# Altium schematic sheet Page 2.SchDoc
size 431 x 279 mm; Date: Not shown in title block; ApprovedBy: Not shown in title block; CheckedBy: Not shown in title block; Author: Not shown in title block; CompanyName: Not shown in title block; Engineer: Not shown in title block; Organization: Not shown in title block; Address1: Not shown in title block; Address2: Not shown in title block; Address3: Not shown in title block; Address4: Not shown in title block; DocumentNumber: 1; Revision: Use project parameter SCH_Rev; SheetNumber: 2; SheetTotal: 3; PageSetup: Record=PageOptions¦CenterHorizontal=True¦CenterVertical=True¦PrintScale=1.00¦XCorrection=1.00¦YCorrection=1.00¦PrintKind=0¦BorderSize=5000000¦LeftOffset=0¦BottomOffset=0¦Orientation=2¦PaperLength=1000¦PaperWidth=1000¦Scale=100¦PaperSource=15¦PrintQuality=600¦MediaType=1¦DitherType=10¦PaperKind=Letter¦PrintScaleMode=1
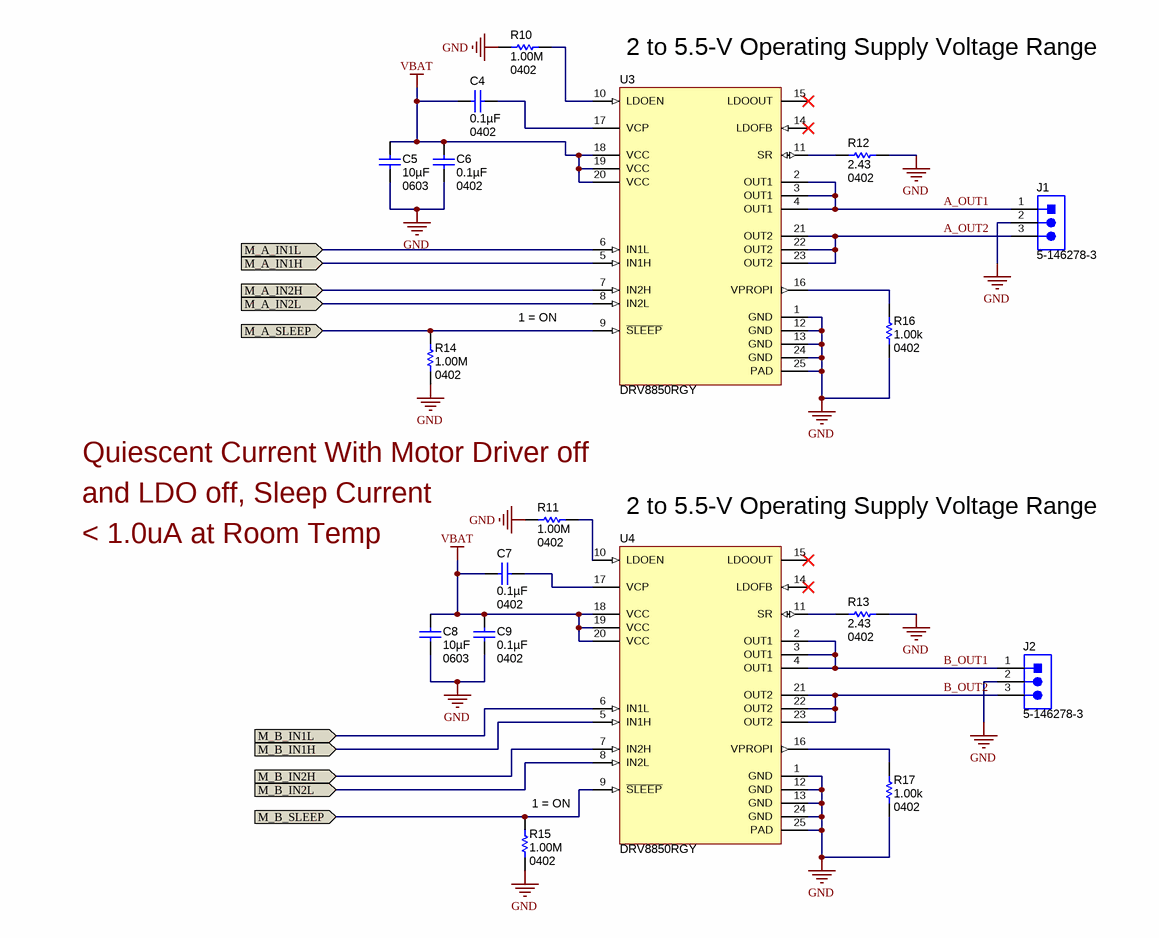
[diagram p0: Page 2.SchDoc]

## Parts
C4  ValueDisplayed: 0.1µF  PackageReference: 0402  [0402L]  (hidden comment: C1005X5R0J104K)
C5  ValueDisplayed: 10µF  PackageReference: 0603  [0603L]  (hidden comment: C1608X5R1E106M080AC)
C6  ValueDisplayed: 0.1µF  PackageReference: 0402  [0402L]  (hidden comment: C1005X5R0J104K)
C7  ValueDisplayed: 0.1µF  PackageReference: 0402  [0402L]  (hidden comment: C1005X5R0J104K)
C8  ValueDisplayed: 10µF  PackageReference: 0603  [0603L]  (hidden comment: C1608X5R1E106M080AC)
C9  ValueDisplayed: 0.1µF  PackageReference: 0402  [0402L]  (hidden comment: C1005X5R0J104K)
J1  5-146278-3  [TE_5-146278-3]
J2  5-146278-3  [TE_5-146278-3]
R10  ValueDisplayed: 1.00M  PackageReference: 0402  [0402L]  (hidden comment: CRCW04021M00FKED)
R11  ValueDisplayed: 1.00M  PackageReference: 0402  [0402L]  (hidden comment: CRCW04021M00FKED)
R12  ValueDisplayed: 2.43  PackageReference: 0402  [0402L]  (hidden comment: CRCW04022R43FKED)
R13  ValueDisplayed: 2.43  PackageReference: 0402  [0402L]  (hidden comment: CRCW04022R43FKED)
R14  ValueDisplayed: 1.00M  PackageReference: 0402  [0402L]  (hidden comment: CRCW04021M00FKED)
R15  ValueDisplayed: 1.00M  PackageReference: 0402  [0402L]  (hidden comment: CRCW04021M00FKED)
R16  ValueDisplayed: 1.00k  PackageReference: 0402  [0402L]  (hidden comment: ERJ-2RKF1001X)
R17  ValueDisplayed: 1.00k  PackageReference: 0402  [0402L]  (hidden comment: ERJ-2RKF1001X)
U3  DRV8850RGY  [RGY0024B]
U4  DRV8850RGY  [RGY0024B]

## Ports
M_A_IN1H (in), M_A_IN1L (in), M_A_IN2H (in), M_A_IN2L (in), M_A_SLEEP (in), M_B_IN1H (in), M_B_IN1L (in), M_B_IN2H (in), M_B_IN2L (in), M_B_SLEEP (in)

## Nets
GND: C5.2 C6.2 C8.2 C9.2 J1.2 J2.2 R10.2 R11.2 R12.1 R13.1 R14.1 R15.1 R16.1 R17.1 U3.1(GND) U3.12(GND) U3.13(GND) U3.24(GND) U3.25(PAD) U4.1(GND) U4.12(GND) U4.13(GND) U4.24(GND) U4.25(PAD)
VBAT: C4.2 C5.1 C6.1 C7.1 C8.1 C9.1 U3.18(VCC) U3.19(VCC) U3.20(VCC) U4.18(VCC) U4.19(VCC) U4.20(VCC)
A_OUT1: J1.1 U3.2(OUT1) U3.3(OUT1) U3.4(OUT1)
A_OUT2: J1.3 U3.21(OUT2) U3.22(OUT2) U3.23(OUT2)
B_OUT1: J2.1 U4.2(OUT1) U4.3(OUT1) U4.4(OUT1)
B_OUT2: J2.3 U4.21(OUT2) U4.22(OUT2) U4.23(OUT2)
M_A_IN1H: U3.5(IN1H) ; port M_A_IN1H
M_A_IN1L: U3.6(IN1L) ; port M_A_IN1L
M_A_IN2H: U3.7(IN2H) ; port M_A_IN2H
M_A_IN2L: U3.8(IN2L) ; port M_A_IN2L
M_A_SLEEP: R14.2 U3.9(~{SLEEP}) ; port M_A_SLEEP
M_B_IN1H: U4.5(IN1H) ; port M_B_IN1H
M_B_IN1L: U4.6(IN1L) ; port M_B_IN1L
M_B_IN2H: U4.7(IN2H) ; port M_B_IN2H
M_B_IN2L: U4.8(IN2L) ; port M_B_IN2L
M_B_SLEEP: R15.2 U4.9(~{SLEEP}) ; port M_B_SLEEP
NetC4_1: C4.1 U3.17(VCP)
NetC7_2: C7.2 U4.17(VCP)
NetR10_1: R10.1 U3.10(LDOEN)
NetR11_1: R11.1 U4.10(LDOEN)
NetR12_2: R12.2 U3.11(SR)
NetR13_2: R13.2 U4.11(SR)
NetR16_2: R16.2 U3.16(VPROPI)
NetR17_2: R17.2 U4.16(VPROPI)

Not connected (* = marked no-connect by the designer): U3 14(LDOFB)* 15(LDOOUT)*; U4 14(LDOFB)* 15(LDOOUT)*

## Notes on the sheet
- (near U3) 2 to 5.5-V Operating Supply Voltage Range
- 1 = ON
- Quiescent Current With Motor Driver off
- < 1.0uA at Room Temp
- and LDO off, Sleep Current
- 2 to 5.5-V Operating Supply Voltage Range
- (near R15) 1 = ON

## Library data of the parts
C4 C6 C7 C9 = C1005X5R0J104K: CAP, CERM, 0.1 µF, 6.3 V, +/- 10%, X5R, 0402; Manufacturer: TDK; Polarized: N; CompType: Capacitor; Value: 0.1uF; U/M: EA; Cap_F: 0.0000001; Tolerance_%: 10; ESR_ohm: 0.0186; Value1: 0.0186 ohm; VDC_V: 6.3; Value2: 6.3V; TaMin_C: -55; TaMax_C: 85
C5 C8 = C1608X5R1E106M080AC: CAP, CERM, 10 µF, 25 V, +/- 20%, X5R, 0603; Manufacturer: TDK; Polarized: N; CompType: Capacitor; Value: 10uF; U/M: EA; Cap_F: 0.00001; Tolerance_%: 20; Value1: Unknown; VDC_V: 25; Value2: 25V; TaMin_C: -55; TaMax_C: 85
J1 J2 = 5-146278-3: Header, 100mil, 3x1, Tin, TH; Manufacturer: TE Connectivity; SymbolCreator: a0799628; U/M: EA
R10 R11 = CRCW04021M00FKED: RES, 1.00 M, 1%, 0.063 W, 0402; Manufacturer: Vishay-Dale; CompType: Resistor; Res_ohm: 1000000; Value: 1.00Meg; Value_Code: 1M00; Tolerance_%: 1; Power_W: 0.063; Value2: 0.063W; VDC_V: 50; TempCo: 100 ppm/C; EIA_Code: E96; U/M: EA
R12 R13 = CRCW04022R43FKED: RES, 2.43, 1%, 0.063 W, 0402; Manufacturer: Vishay-Dale; CompType: Resistor; Value: 2.43; Value_Code: 2R43; Tolerance_%: 1; Power_W: 0.063; Value2: 0.063W; VDC_V: 50; TempCo: 100 ppm/C; EIA_Code: E96; U/M: EA
R14 R15 = CRCW04021M00FKED: RES, 1.00 M, 1%, 0.063 W, 0402; Manufacturer: Vishay-Dale; CompType: Resistor; Value: 1.00Meg; Res_ohm: 1000000; Value_Code: 1M00; Tolerance_%: 1; Power_W: 0.063; Value2: 0.063W; VDC_V: 50; TempCo: 100 ppm/C; EIA_Code: E96; U/M: EA
R16 R17 = ERJ-2RKF1001X: RES, 1.00 k, 1%, 0.1 W, 0402; Manufacturer: Panasonic; CompType: Resistor; Res_ohm: 1000; Value: 1.00k; Value_Code: 1k00; Tolerance_%: 1; Power_W: 0.1; Value2: 0.1W; VDC_V: 50; TempCo: 100 ppm/C; EIA_Code: E96; U/M: EA
U3 U4 = DRV8850RGY: Low-Voltage H-Bridge IC With LDO Regulator, RGY0024B; Alternate Manufacturer: None; Manufacturer: Texas Instruments; SymbolCreator: a0411947; U/M: EA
